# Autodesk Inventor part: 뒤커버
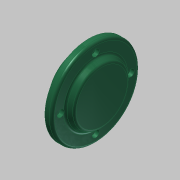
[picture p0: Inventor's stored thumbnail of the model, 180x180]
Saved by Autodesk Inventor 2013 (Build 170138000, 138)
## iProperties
Created: 2015-11
Part Number: 뒤커버
Material: 일반
Document SubType Name: Modeling
Designer: mduedu
Density: 1 g/cm^3
Mass: 114.066 g
Surface Area: 231.216 cm^2
Volume: 114.066 cm^3
Author: mduedu
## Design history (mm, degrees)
sketch "스케치1"
  geometry: C1 r 50 at (0, 0); 1 further point
  constraints: 1 centre point, 1 coincident
  dimensions: "d42" = 100 diameter of C1
extrude "돌출1" new body sketch "스케치1" distance "d3" = 8; taper "d4" = 0 deg
sketch "스케치2"
  geometry: C1 r 35 at (0, 0); 1 further point
  constraints: 1 centre point, 1 coincident
  dimensions: "d5" = 70 diameter of C1
extrude "돌출2" join sketch "스케치2" distance "d6" = 7; taper "d7" = -30 deg
sketch "스케치5" dims "d44" = 80
  geometry: 3 further points
  constraints: 2 vertical alignment, 1 coincident, 2 other
hole "구멍3" sketch "스케치5" at (0, 40) diameter "d45" = 4.5; stored, may be unused: countersink angle "d49" = 90 deg, drill point angle "d51" = 118 deg; dims "d46" = 6, "d47" = 8, "d48" = 4.4, "d50" = 8
sketch "스케치4"
  geometry: C1 r 35 at (0, 0); 1 further point
  constraints: 1 centre point, 1 coincident
  dimensions: "d21" = 70 diameter of C1
extrude "돌출3" join sketch "스케치4" distance "d23" = 12; taper "d24" = 0 deg
hole "구멍2" diameter "d27" = 30; stored, may be unused: countersink angle "d31" = 90 deg, drill point angle "d33" = 0 deg; dims "d25" = 10, "d26" = 10, "d28" = 6, "d29" = 40, "d30" = 12, "d32" = 15
fillet "모깎기3" dims "d36" = 3
fillet "모깎기4" dims "d37" = 3
fillet "모깎기5" dims "d38" = 0.3
chamfer "모따기1" distance "d39" = 1; stored, may be unused: second distance "d40" = 2, angle "d41" = 45 deg
node "솔리드1"
pattern_circular "원형 패턴2" dims angle "d53" = 360 deg
